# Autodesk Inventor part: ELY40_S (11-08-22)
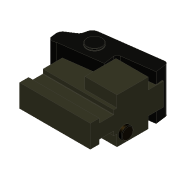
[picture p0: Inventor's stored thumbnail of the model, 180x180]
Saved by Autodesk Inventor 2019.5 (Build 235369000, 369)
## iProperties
Created: 2022-08
Part Number: ELY40_S (11-08-22)
Material: St37-2 / S235
Document SubType Name: Modeling
Designer: schoth
Density: 7.86 g/cm^3
Appearance: Steel
RuleStatus: InUse
Author: schoth
Mass(KG): 0.0
Area(mm): 0.0
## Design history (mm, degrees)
derived "ELY40.iam"
body "Solid1"
node "FB185-005.ipt:1"
node "ELY40-88.iam:1::FB189-030.ipt:1"
node "ELY40-88.iam:1::CS235-006.ipt:1"
node "ELY40-99.iam:1::FB186-011.ipt:1"
node "ELY40-99.iam:1::FB187-104.ipt:1"
node "ELY40.iam_Bodies"
